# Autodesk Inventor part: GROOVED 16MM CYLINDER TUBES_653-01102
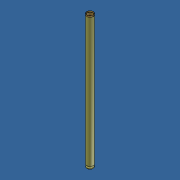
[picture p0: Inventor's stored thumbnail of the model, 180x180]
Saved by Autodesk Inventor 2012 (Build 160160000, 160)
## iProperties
Created: 2013-10
Part Number: GROOVED 16MM CYLINDER TUBES_653-01102
Material: Steel
Document SubType Name: Modeling
Designer: Admin
Density: 7.85 g/cm^3
Mass: 124.558 g
Surface Area: 319.12 cm^2
Volume: 15.8673 cm^3
Author: Admin
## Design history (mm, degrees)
node "GROOVED 16MM CYLINDER TUBES_653-011021"
node "Base1"
body "Solid1"
